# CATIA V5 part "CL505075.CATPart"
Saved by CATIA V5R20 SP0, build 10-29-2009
Part number: CL505075
Bounding box of the stored display mesh (mm): x -37.5 to 37.5, y -56 to 0, z -18 to 18
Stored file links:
  C:\Users\Raffaele\Desktop\3D X SITO CF\BOLEX\17-CENTERER REF 505\CL505075.CATPart
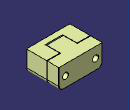
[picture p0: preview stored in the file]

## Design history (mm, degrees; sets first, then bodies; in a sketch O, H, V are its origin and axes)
Set1
  DatumSurface1 to DatumSurface111 "MANIFOLD_SOLID_BREP #3007"
  DatumSurface112 to DatumSurface115 "MANIFOLD_SOLID_BREP #3095"
  DatumSurface116 to DatumSurface119 "MANIFOLD_SOLID_BREP #3183"
  DatumSurface120 to DatumSurface123 "MANIFOLD_SOLID_BREP #3271"
  DatumSurface124 to DatumSurface127 "MANIFOLD_SOLID_BREP #3359"
  DatumSurface128 to DatumSurface131 "MANIFOLD_SOLID_BREP #3447"
  DatumSurface132 to DatumSurface135 "MANIFOLD_SOLID_BREP #3535"
  DatumSurface136 to DatumSurface139 "MANIFOLD_SOLID_BREP #3623"
  DatumSurface140 to DatumSurface143 "MANIFOLD_SOLID_BREP #3711"
  DatumSurface144 to DatumSurface147 "MANIFOLD_SOLID_BREP #3799"
  DatumSurface148 to DatumSurface151 "MANIFOLD_SOLID_BREP #3887"
  DatumSurface152 to DatumSurface155 "MANIFOLD_SOLID_BREP #3975"
  DatumSurface156 to DatumSurface159 "MANIFOLD_SOLID_BREP #4063"
  DatumSurface160 to DatumSurface163 "MANIFOLD_SOLID_BREP #4151"
  DatumSurface164 to DatumSurface167 "MANIFOLD_SOLID_BREP #4239"
  DatumSurface168 to DatumSurface171 "MANIFOLD_SOLID_BREP #4327"
  DatumSurface172 to DatumSurface175 "MANIFOLD_SOLID_BREP #4415"
  DatumSurface176 to DatumSurface179 "MANIFOLD_SOLID_BREP #4503"
  DatumSurface180 to DatumSurface183 "MANIFOLD_SOLID_BREP #4591"
  DatumSurface184 to DatumSurface187 "MANIFOLD_SOLID_BREP #4679"
  DatumSurface188 to DatumSurface191 "MANIFOLD_SOLID_BREP #4767"
  DatumSurface192 to DatumSurface195 "MANIFOLD_SOLID_BREP #4855"
  DatumSurface196 to DatumSurface199 "MANIFOLD_SOLID_BREP #4943"
  DatumSurface200 to DatumSurface203 "MANIFOLD_SOLID_BREP #5031"
  DatumSurface204 to DatumSurface207 "MANIFOLD_SOLID_BREP #5119"
  DatumSurface208 to DatumSurface236 "MANIFOLD_SOLID_BREP #6011"
Body1 (main body)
